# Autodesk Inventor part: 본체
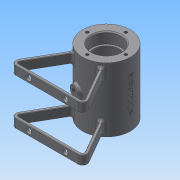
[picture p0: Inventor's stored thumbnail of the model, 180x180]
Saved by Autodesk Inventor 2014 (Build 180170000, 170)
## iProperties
Created: 2016-03
Part Number: 본체
Material: 일반
Document SubType Name: Modeling
Designer: 406-0014
Density: 1 g/cm^3
Appearance: 기본값
Author: 406-0014
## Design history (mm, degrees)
sketch "스케치1"
  geometry: C1 r 26 at (0, 0); 1 further point
  constraints: 1 centre point, 1 coincident
  dimensions: "d0" = 52 diameter of C1
extrude "돌출1" new body sketch "스케치1" distance "d1" = 70; taper "d2" = 0 deg
node "작업 평면1"
sketch "스케치2"
  geometry: L1 (26, 70)-(-26, 70) reference; C1 r 5 at (0, 35); 1 further point
  constraints: 1 centre point
  dimensions: "d5" = 10 diameter of C1; "d6" = 35 distance from line of L1 C1.centre; "d7" = 0 horizontal distance of point (0, 0) C1.centre
extrude "돌출2" join sketch "스케치2" stored distance "d8" = 70; taper "d9" = 0 deg
sketch "스케치3"
  geometry: L1 (26, 70)-(-26, 70) reference; L2 (-26, 0)-(26, 0) reference; L3 (0, 0)-(0, 70); L4 (0, 70)-(16, 70); L5 (16, 70)-(16, 58); L6 (16, 58)-(14, 58); L7 (14, 58)-(14, 56); L8 (14, 56)-(18, 56); L9 (21, 53)-(21, 17); L10 (18, 14)-(14, 14); L11 (14, 14)-(14, 12); L12 (14, 12)-(16, 12); L13 (16, 12)-(16, 0); L14 (16, 0)-(0, 0); A1 r 3 centre (18, 53) between (21, 53) and (18, 56); A2 r 3 centre (18, 17) between (18, 14) and (21, 17); 2 further points
  constraints: 24 end point, 7 perpendicular, 6 point on line, 4 point on circle, 4 tangent, 3 parallel, 2 centre point, 1 equal radius, 1 midpoint
  dimensions: "d10" = 32 diameter of L5 L3; "d11" = 28 diameter of L7 L3; "d12" = 42 diameter of L9 L3; "d13" = 28 diameter of L11 L3; "d14" = 32 diameter of L13 L3; "d15" = 12 distance of L4.end L5.end; "d17" = 12 distance of L13.end L12.end; "d18" = 2 vertical distance of L5.end point (21, 56); "d19" = 2 vertical distance of L12.end point (21, 14); "d20" = 3 radius of A1
revolve "회전1" sketch "스케치3" stored, may be unused: angle "d21" = 90 deg
node "작업 평면3"
  node "작업 평면2"
sketch "스케치7"
  geometry: L1 (0, 33.323)-(0, -33.323); L2 (0, 0)-(-7.506, -28.012); C1 r 26 at (0, 0) reference; 2 further points
  constraints: 4 end point, 2 coincident, 1 midpoint, 1 vertical
  dimensions: "d95" = 15 deg angle of L1 L2; "d96" = 29 distance of L2.start L2.end
sketch "스케치9"
  geometry: C1 r 5 at (0, 0) reference; 2 further points
  constraints: 1 coincident
hole "구멍1" sketch "스케치9" at (0, 0) diameter "d46" = 5.188; stored, may be unused: countersink angle "d50" = 90 deg, drill point angle "d52" = 118 deg; dims "d47" = 19, "d48" = 4, "d49" = 2, "d51" = 20
sketch "스케치11"
  geometry: L1 (34.867, -64.517)-(10.311, -23.868) reference; C1 r 16 at (0, 0) reference; C2 r 21 at (0, 0); 5 further points
  constraints: 1 centre point, 1 coincident, 6 other
  dimensions: "d60" = 42 diameter of C2; "d61" = 21 distance of C1.centre point (0, 21); "d62" = 34.86707 horizontal distance of point (0, 21) L1.start; "d65" = 360 deg dimension on C1.centre point (0, 21) (derived)
hole "구멍3" sketch "스케치11" at (0, 21), (-21, 0), (0, -21), (21, 0) diameter "d67" = 3.242; stored, may be unused: countersink angle "d71" = 90 deg, drill point angle "d73" = 118 deg; dims "d68" = 8, "d69" = 4, "d70" = 2, "d72" = 10
chamfer "모따기1" distance "d74" = 1; stored, may be unused: second distance "d75" = 2, angle "d76" = 45 deg
fillet "모깎기1" dims "d77" = 0.3
fillet "모깎기3" dims "d87" = 2
node "작업 평면5"
node "작업 평면6"
sketch "스케치17"
  geometry: L1 (26, 70)-(-26, 70) reference; L2 (26, 0)-(26, 70) reference; 2 further points
  constraints: 1 other
  dimensions: "d110" = 26 distance from line of L2 point (0, 35); "d111" = 35 distance from line of L1 point (0, 35)
feature "엠보싱1" sketch "스케치17" dims "d10" = 32, "d11" = 28, "d12" = 42, "d13" = 28, "d14" = 32, "d15" = 12, "d17" = 12, "d18" = 2, "d19" = 2, "d20" = 3, "d112" = 0.5, "d113" = 0
sketch "스케치18"
  geometry: L1 (-26, 0)-(26, 0); L2 (-42.594, -65)-(42.594, -65); L3 (0, 26)-(0, -26); L4 (-42.594, -65)-(-16.613, -20); L5 (42.594, -65)-(16.613, -20); A1 r 26 centre (0, 0) between (26, 0) and (-26, 0) reference; 1 further point
  constraints: 10 end point, 6 point on circle, 2 midpoint, 1 horizontal, 1 parallel, 1 perpendicular
  dimensions: "d114" = 65 vertical distance of L2.end L1.end; "d115" = 30 deg angle of L3 L4; "d116" = 30 deg angle of L3 L5; "d117" = 45 vertical distance of L2.end L5.end; "d118" = 45 vertical distance of L2.start L4.end
extrude "돌출10" join sketch "스케치18" distance "d119" = 10; taper "d120" = 0 deg
node "작업 평면7"
fillet "모깎기8" dims "d121" = 5
sketch "스케치21"
  geometry: L1 (-26, 0)-(26, 0); L2 (0, 0)-(-7.506, -28.012); L3 (0, 26)-(0, -26); A1 r 26 centre (0, 0) between (26, 0) and (-26, 0) reference; 3 further points
  constraints: 6 end point, 4 point on circle, 3 midpoint, 1 coincident, 1 horizontal, 1 perpendicular
  dimensions: "d130" = 15 deg angle of L3 L2; "d131" = 29 distance of L2.start L2.end
fillet "모깎기12" dims "d147" = 0.5
sketch "스케치24"
  geometry: L1 (67.868, 0)-(0, 0) reference; L2 (50.154, 44.18)-(71.765, 6.75) reference; L3 (17.321, 44.5)-(-4.33, 7) reference; L4 (19.751, 42.709)-(-1.732, 5.5); L5 (0, 2.5)-(67.868, 2.5); L6 (69.6, 5.5)-(48.117, 42.709); A1 r 4.5 centre (0, 4.5) between (-3.897, 6.75) and (0, 0) reference; A2 r 4.5 centre (67.868, 4.5) between (67.868, 0) and (71.765, 6.75) reference; A3 r 2 centre (0, 4.5) between (-1.732, 5.5) and (0, 2.5); A4 r 2 centre (67.868, 4.5) between (67.868, 2.5) and (69.6, 5.5); A5 r 26 centre (33.934, 64.5) between (19.751, 42.709) and (48.117, 42.709) reference; 2 further points
  constraints: 6 end point, 6 point on circle, 2 centre point, 2 tangent, 1 parallel, 2 other
  dimensions: "d148" = 3 distance between parallel lines of L3 L4
extrude "돌출14" cut sketch "스케치24" distance "d149" = 100; taper "d150" = 0 deg
sketch "스케치25"
  geometry: L1 (67.868, 0)-(0, 0) reference; L2 (0, 9)-(67.868, 9) reference; L3 (33.934, 9)-(33.934, 0); L4 (67.868, 9.5)-(0, 9.5) reference; C1 r 3 at (13.934, 4.5); C2 r 3 at (53.934, 4.5); 1 further point
  constraints: 2 centre point, 2 end point, 2 midpoint, 1 symmetric about line, 1 other
  dimensions: "d151" = 6 diameter of C1; "d152" = 20 horizontal distance of C1.centre L3.start; "d169" = 5 distance from line of L4 C1.centre
extrude "돌출15" cut sketch "스케치25" distance "d154" = 10; taper "d155" = 0 deg
sketch "스케치26"
  geometry: L1 (-26, -35)-(-26, 35) reference; L2 (26, 35)-(-26, 35) reference; C1 r 6 at (0, 0); 1 further point
  constraints: 1 centre point
  dimensions: "d156" = 12 diameter of C1; "d157" = 35 distance from line of C1.centre L2; "d158" = 26 distance from line of C1.centre L1
extrude "돌출16" join sketch "스케치26" stored distance "d159" = 10; taper "d160" = 0 deg
fillet "모깎기13" dims "d161" = 2
sketch "스케치27"
  geometry: C1 r 6 at (0, 0) reference; 2 further points
  constraints: 1 coincident
hole "구멍6" sketch "스케치27" at (0, 0) diameter "d162" = 5.188; stored, may be unused: countersink angle "d166" = 90 deg, drill point angle "d168" = 118 deg; dims "d163" = 19, "d164" = 4, "d165" = 2, "d167" = 20
fillet "모깎기14" dims "d170" = 0.5
fillet "모깎기15" dims "d171" = 3
node "솔리드1"
mirror "대칭2"
mirror "대칭5"
mirror "대칭7"
other parameters: "d3" = 29
